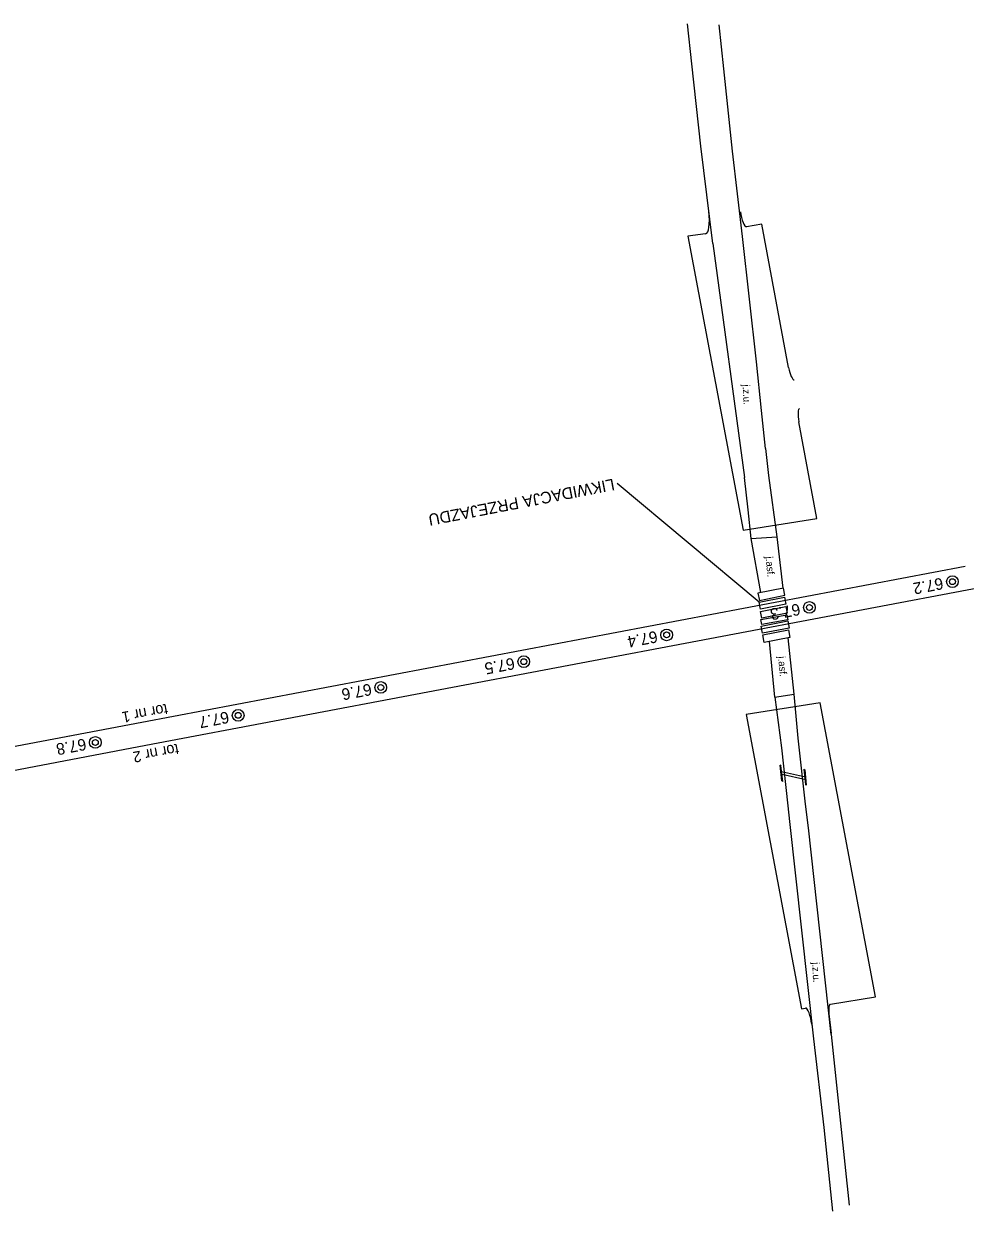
# Model space of a CAD drawing. Extents: x 6541740 to 6556805, y 5525233 to 5530361.
# Drawn here: x 6555641.5 to 6555803.5, y 5525790.3 to 5525994.7 of the extents above; entities that cross this region are included whole.
import ezdxf

# ---------------------------------------------------------------- set-up
doc = ezdxf.new("R2010")
doc.units = 0
for name, color, linetype in [('Default', 7, 'Continuous'), ('TOR_PS_OPIS_T-numeracja torow i rozjazdow', 7, 'Continuous'), ('TOR_SCH-hektometry', 7, 'Continuous'), ('TOR_SCH-obiekty istniejace', 7, 'Continuous'), ('TOR_SCH-opisy dodatkowe', 7, 'Continuous'), ('TOR_SCH-przejazdy+drogi istniejace', 7, 'Continuous'), ('TOR_SCH-przejazdy+drogi projektowane', 7, 'Continuous'), ('TOR_SCH-tory projektowane', 7, 'Continuous')]:
    doc.layers.add(name, color=color, linetype=linetype)

# ---------------------------------------------------------------- blocks, each defined once
blk = doc.blocks.new('4010_1')
at = {"layer": 'Default'}
for radius in [0.75, 0.375]:
    blk.add_circle((0, 0), radius, dxfattribs=at)

msp = doc.modelspace()

# ---------------------------------------------------------------- linework, layer by layer
at = {"layer": 'TOR_SCH-obiekty istniejace'}
for p, q in [((6555771.96, 5525864.37), (6555771.66, 5525867.09)), ((6555771.81, 5525866.97), (6555771.67, 5525867.09)), ((6555772.1, 5525864.24), (6555771.8, 5525866.97)), ((6555771.91, 5525865.99), (6555776, 5525865.07)), ((6555775.75, 5525866.38), (6555775.9, 5525866.24)), ((6555775.75, 5525866.38), (6555776.01, 5525863.76)), ((6555775.9, 5525866.24), (6555776.15, 5525863.61)), ((6555772.1, 5525864.24), (6555771.96, 5525864.37)), ((6555771.98, 5525865.53), (6555776.07, 5525864.61)), ((6555776.01, 5525863.76), (6555776.15, 5525863.61))]:
    msp.add_line(p, q, dxfattribs=at)
at = {"layer": 'TOR_SCH-opisy dodatkowe'}
msp.add_lwpolyline([(6555768.02, 5525895.11), (6555743.61, 5525915.52)], dxfattribs=at)
at = {"layer": 'TOR_SCH-przejazdy+drogi istniejace'}
for p, q in [((6555767.59, 5525936.47), (6555765.19, 5525958.06)), ((6555760.06, 5525956.83), (6555765.51, 5525916.58)), ((6555768.47, 5525928.08), (6555767.59, 5525936.47)), ((6555769.16, 5525921.56), (6555768.47, 5525928.08)), ((6555772.99, 5525860.07), (6555773.26, 5525857.37)), ((6555776.52, 5525856.29), (6555776.03, 5525860.35)), ((6555773.26, 5525857.37), (6555777.38, 5525819.98)), ((6555780.41, 5525820.69), (6555776.52, 5525856.29))]:
    msp.add_line(p, q, dxfattribs=at)
for points in [[(6555760.06, 5525956.83), (6555757.99, 5525973.6), (6555756.48, 5525987.76), (6555755.74, 5525994.66)], [(6555765.19, 5525958.06), (6555763.47, 5525972.76), (6555761.95, 5525986.91), (6555761.15, 5525994.49)], [(6555769.16, 5525921.56), (6555769.65, 5525916.94), (6555771.07, 5525906.39)], [(6555766.7, 5525906.09), (6555766.13, 5525911.03), (6555765.51, 5525916.58)], [(6555768.35, 5525896.76), (6555766.7, 5525906.09), (6555771.07, 5525906.39), (6555772.11, 5525897.5)], [(6555769.79, 5525888.36), (6555770.71, 5525878.75), (6555774.06, 5525879.29), (6555773.05, 5525888.96)], [(6555770.75, 5525878.76), (6555771.88, 5525870.04), (6555772.99, 5525860.07)], [(6555776.03, 5525860.35), (6555774.74, 5525871.71), (6555774.06, 5525879.29)], [(6555780.41, 5525820.69), (6555782.05, 5525805.45), (6555783.53, 5525791.36)], [(6555777.38, 5525819.98), (6555779.16, 5525804.73), (6555780.67, 5525790.29)]]:
    msp.add_lwpolyline(points, dxfattribs=at)
for points in [[(6555768.08, 5525895.42), (6555772.48, 5525896.31), (6555772.23, 5525897.55), (6555767.83, 5525896.66)], [(6555768.02, 5525895.11), (6555772.43, 5525895.99), (6555772.66, 5525894.78), (6555768.26, 5525893.9)], [(6555768.25, 5525893.54), (6555772.62, 5525894.38), (6555772.84, 5525893.2), (6555768.48, 5525892.36)], [(6555768.36, 5525892.12), (6555772.83, 5525892.94), (6555772.98, 5525892.1), (6555768.52, 5525891.28)], [(6555768.41, 5525891.01), (6555772.97, 5525891.88), (6555773.21, 5525890.65), (6555768.64, 5525889.78)], [(6555768.65, 5525889.47), (6555773.09, 5525890.33), (6555773.35, 5525889.03), (6555768.9, 5525888.17)]]:
    msp.add_lwpolyline(points, close=True, dxfattribs=at)
at = {"layer": 'TOR_SCH-przejazdy+drogi projektowane'}
for p, q in [((6555780.05, 5525824.28), (6555780.43, 5525820.88)), ((6555777.1, 5525822.51), (6555777.21, 5525821.52))]:
    msp.add_line(p, q, dxfattribs=at)
for points in [[(6555773.12, 5525935.5), (6555768.49, 5525960.15), (6555765.86, 5525959.73)], [(6555758.82, 5525958.51), (6555755.77, 5525958.11), (6555765.28, 5525907.49), (6555777.99, 5525909.54), (6555774.87, 5525926.17)], [(6555780.29, 5525825.95), (6555788.04, 5525827.2), (6555778.53, 5525877.81), (6555765.82, 5525875.77), (6555775.32, 5525825.15), (6555776.03, 5525825.27)]]:
    msp.add_lwpolyline(points, dxfattribs=at)
for centre, major_axis, start_param, end_param in [((6555757.86, 5525963.67), (-0.98, 5.16), 3.13466, 4.413441), ((6555765.45, 5525961.94), (-0.42, 2.21), 1.357407, 3.13466), ((6555773.67, 5525935.59), (-0.42, 2.21), 1.563864, 3.13466), ((6555775.43, 5525926.25), (-0.42, 2.21), 6.276253, 7.847049), ((6555776.44, 5525823.05), (-0.42, 2.21), 4.416725, 6.276253), ((6555780.7, 5525823.74), (0.42, -2.21), 3.13466, 4.416725)]:
    msp.add_ellipse(centre, major_axis=major_axis, ratio=0.25, start_param=start_param, end_param=end_param, dxfattribs=at)
at = {"layer": 'TOR_SCH-tory projektowane'}
for p, q in [((6555909.41, 5525917.23), (6555662.57, 5525870.44)), ((6555803.5, 5525901.28), (6555661.88, 5525874.43)), ((6555661.88, 5525874.43), (6555417.84, 5525828.17)), ((6555662.57, 5525870.44), (6555511.67, 5525841.84))]:
    msp.add_line(p, q, dxfattribs=at)

# ---------------------------------------------------------------- block references
at = {"layer": 'TOR_SCH-hektometry', "xscale": 1.345963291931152, "yscale": 1.345963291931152}
for p in [(6555801.29, 5525898.65), (6555776.69, 5525894.21), (6555752.13, 5525889.49), (6555727.56, 5525884.88), (6555702.96, 5525880.44), (6555678.43, 5525875.64), (6555653.86, 5525870.98)]:
    msp.add_blockref('4010_1', p, dxfattribs=at)

# ---------------------------------------------------------------- texts
at = {"layer": 'TOR_PS_OPIS_T-numeracja torow i rozjazdow'}
for s, p in [('tor nr 1', (6555666.11, 5525877.65)), ('tor nr 2', (6555668.01, 5525870.79))]:
    msp.add_text(s, height=1.875, rotation=190.7101, dxfattribs=at).set_placement(p)
at = {"layer": 'TOR_SCH-hektometry'}
for s, p in [('67.2', (6555799.5, 5525899.36)), ('67.3', (6555774.91, 5525894.92)), ('67.4', (6555750.36, 5525890.2)), ('67.5', (6555725.79, 5525885.59)), ('67.6', (6555701.19, 5525881.14)), ('67.7', (6555676.65, 5525876.34)), ('67.8', (6555652.09, 5525871.69))]:
    msp.add_text(s, height=2, rotation=190.7691, dxfattribs=at).set_placement(p)
at = {"layer": 'TOR_SCH-opisy dodatkowe'}
msp.add_text('LIKWIDACJA PRZEJAZDU', height=2, rotation=190.9433, dxfattribs=at).set_placement((6555742.95, 5525916.39))
at = {"layer": 'TOR_SCH-przejazdy+drogi istniejace'}
for s, height, rotation, p in [('j.z.u.', 1.231, 272.9234, (6555765.2, 5525932.55)), ('j.asf.', 1.25, 275.1715, (6555769.16, 5525902.93)), ('j.asf.', 1.25, 275.1715, (6555771.29, 5525885.75)), ('j.z.u.', 1.231, 272.9234, (6555777.16, 5525833.12))]:
    msp.add_text(s, height=height, rotation=rotation, dxfattribs=at).set_placement(p)

doc.saveas('drawing.dxf')
